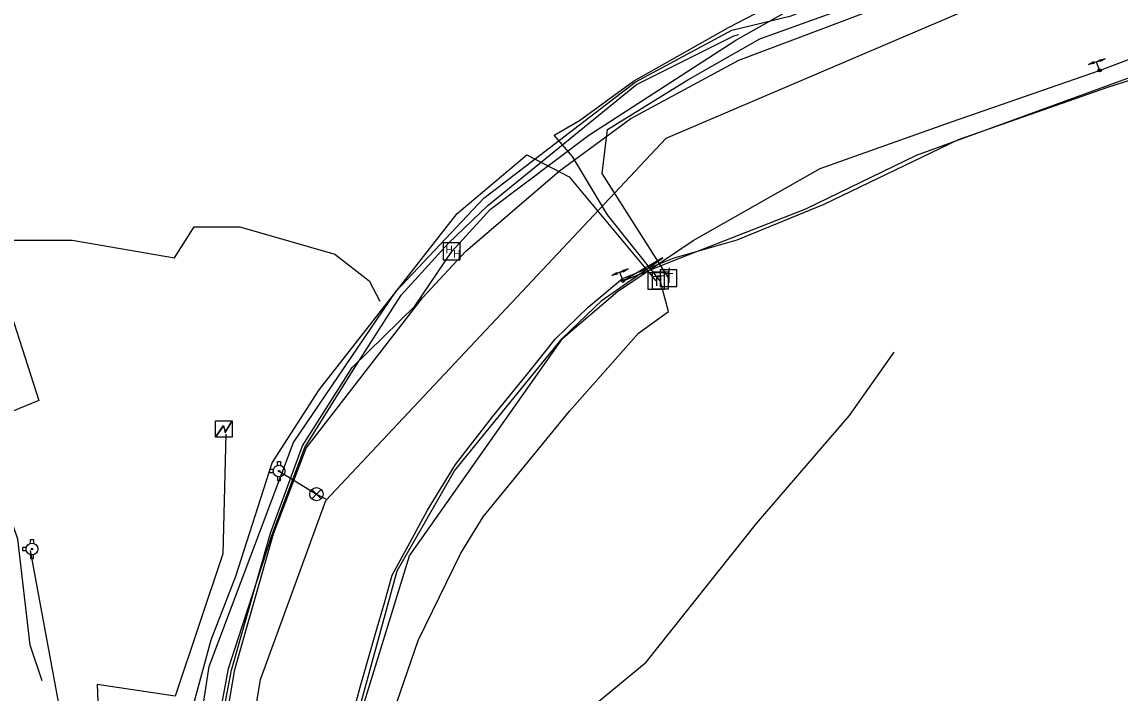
# Model space of a CAD drawing. Extents: x 2070721 to 2083039, y 729290 to 737883.
# Drawn here: x 2080173.8 to 2080544.7, y 734315.9 to 734542.4 of the extents above; entities that cross this region are included whole.
import ezdxf

# ---------------------------------------------------------------- set-up
doc = ezdxf.new("R2010")
doc.units = 0
for name, color, linetype in [('COGO Default Point Elevation', 7, 'Continuous'), ('COGO Default Point Number', 7, 'Continuous'), ('Exist Utilities Power Pole CELL', 7, 'Continuous'), ('Exist Utilities Power Pole Cogo Elevation', 7, 'Continuous'), ('Exist Utilities Power UG Cable Cogo Point CELL', 7, 'Continuous'), ('Exist Utilities Telephone UG Cable SUE LOS C Cogo Comment', 7, 'Continuous'), ('Exist Utilities Telephone UG Cable SUE LOS C Cogo Number', 7, 'Continuous'), ('Exist Utilities Telephone UG FO SUE LOS B Cogo Comment', 7, 'Continuous'), ('Exist Utilities Telephone UG FO SUE LOS B Cogo Number', 7, 'Continuous'), ('Exist Utilities TV Pedestal CELL', 7, 'Continuous'), ('Exist Utilities TV Pedestal Cogo Elevation', 7, 'Continuous'), ('Exist Utilities TV UG Cable Cogo Point CELL', 7, 'Continuous'), ('Exist Utilities TV UG Cable SUE LOS C Cogo Comment', 7, 'Continuous'), ('Exist Utilities TV UG Cable SUE LOS C Cogo Number', 7, 'Continuous'), ('Exist Utilities TV UG Cable SUE LOS C Cogo Point CELL', 7, 'Continuous'), ('Exist Utilities Water UG Line SUE LOS B Cogo Elevation', 7, 'Continuous'), ('Exist Utilities Water Valve CELL', 7, 'Continuous')]:
    doc.layers.add(name, color=color, linetype=linetype)

msp = doc.modelspace()

# ---------------------------------------------------------------- linework, layer by layer
at = {"layer": 'COGO Default Point Elevation'}
msp.add_lwpolyline([(2080274.88, 734384.58), (2080271.73, 734381.43), (2080273.3, 734383), (2080274.88, 734381.43), (2080271.73, 734384.58)], dxfattribs=at)
msp.add_circle((2080273.3, 734383), 2.23, dxfattribs=at)
at = {"layer": 'COGO Default Point Number'}
for p, q in [((2080260.69, 734390.79), (2080260.69, 734390.79)), ((2080177.24, 734364.47), (2080177.24, 734364.47))]:
    msp.add_line(p, q, dxfattribs=at)
for points in [[(2080260.18, 734392.7), (2080260.18, 734393.99), (2080261.2, 734393.99), (2080261.2, 734392.68)], [(2080258.78, 734391.3), (2080257.49, 734391.3), (2080257.49, 734390.28), (2080258.78, 734390.28)], [(2080260.18, 734388.88), (2080260.18, 734387.59), (2080261.2, 734387.59), (2080261.2, 734388.9)], [(2080176.73, 734366.38), (2080176.73, 734367.67), (2080177.75, 734367.67), (2080177.75, 734366.36)], [(2080175.33, 734364.98), (2080174.04, 734364.98), (2080174.04, 734363.96), (2080175.33, 734363.96)], [(2080176.73, 734362.56), (2080176.73, 734361.27), (2080177.75, 734361.27), (2080177.75, 734362.58)]]:
    msp.add_lwpolyline(points, dxfattribs=at)
for centre, radius in [((2080260.69, 734390.79), 1.98), ((2080260.69, 734390.79), 0.243), ((2080177.24, 734364.47), 1.98), ((2080177.24, 734364.47), 0.243)]:
    msp.add_circle(centre, radius, dxfattribs=at)
at = {"layer": 'Exist Utilities Power Pole CELL'}
msp.add_lwpolyline([(2080232.24, 734245.67), (2080237.5, 734254.36), (2080238.66, 734282.35), (2080245.75, 734323.83), (2080258.86, 734369.55), (2080269.86, 734398.57), (2080309.08, 734449.32), (2080323.63, 734464.88), (2080355.41, 734492.16), (2080379.52, 734509.8), (2080416.03, 734529.49), (2080502.71, 734562.3), (2080573.96, 734587.12), (2080616.57, 734603.22), (2080677.16, 734624.99), (2080749, 734651.22), (2080815.57, 734674.3), (2080861.11, 734690.56), (2080923.26, 734714.15), (2080934.26, 734720.97)], dxfattribs=at)
at = {"layer": 'Exist Utilities Power Pole Cogo Elevation'}
msp.add_lwpolyline([(2080537.8, 734526.08), (2080558.84, 734534.05), (2080639.7, 734564.08), (2080660.56, 734567.92), (2080667.78, 734563.47)], dxfattribs=at)
at = {"layer": 'Exist Utilities Power UG Cable Cogo Point CELL'}
for p, q in [((2080539.74, 734530.03), (2080534.11, 734528.06)), ((2080536.78, 734529), (2080539.74, 734530.03)), ((2080537.8, 734526.08), (2080536.78, 734529)), ((2080537.8, 734526.08), (2080537.8, 734526.08))]:
    msp.add_line(p, q, dxfattribs=at)
for points in [[(2080539.74, 734530.03), (2080537.99, 734529.06), (2080538.28, 734529.52), (2080537.82, 734529.68)], [(2080534.11, 734528.06), (2080535.86, 734529.04), (2080535.58, 734528.58), (2080536.04, 734528.41)]]:
    msp.add_lwpolyline(points, close=True, dxfattribs=at)
msp.add_circle((2080537.8, 734526.08), 0.517, dxfattribs=at)
at = {"layer": 'Exist Utilities Telephone UG Cable SUE LOS C Cogo Comment'}
msp.add_lwpolyline([(2080237.92, 734293.08), (2080243.61, 734324.09), (2080258.34, 734369.36), (2080269.39, 734398.77), (2080286.02, 734425.45), (2080301.91, 734450.14), (2080317.89, 734467.75), (2080331.23, 734480.5), (2080381.43, 734521.31), (2080414.27, 734537.75), (2080416.02, 734538.24)], dxfattribs=at)
at = {"layer": 'Exist Utilities Telephone UG Cable SUE LOS C Cogo Number'}
msp.add_line((2080242.08, 734405.14), (2080242.08, 734405.14), dxfattribs=at)
msp.add_lwpolyline([(2080239.24, 734407.75), (2080244.79, 734407.75), (2080244.79, 734402.2), (2080239.24, 734402.2)], close=True, dxfattribs=at)
for points in [[(2080239.24, 734402.2), (2080241.88, 734406.14), (2080242.51, 734403.93), (2080244.79, 734407.75)], [(2080239.31, 734402.2), (2080241.88, 734405.93), (2080242.47, 734403.75), (2080244.79, 734407.6)]]:
    msp.add_lwpolyline(points, dxfattribs=at)
at = {"layer": 'Exist Utilities Telephone UG FO SUE LOS B Cogo Comment'}
for p, q in [((2080392.18, 734455.98), (2080392.18, 734455.98)), ((2080387.98, 734454.99), (2080387.98, 734454.99)), ((2080389.38, 734455.18), (2080389.38, 734455.18))]:
    msp.add_line(p, q, dxfattribs=at)
for points in [[(2080385.26, 734452.16), (2080390.85, 734452.16), (2080390.85, 734457.76), (2080385.26, 734457.76), (2080385.26, 734452.16)], [(2080386.66, 734452.35), (2080392.25, 734452.35), (2080392.25, 734457.95), (2080386.66, 734457.95), (2080386.66, 734452.35)], [(2080389.46, 734453.15), (2080395.05, 734453.15), (2080395.05, 734458.75), (2080389.46, 734458.75), (2080389.46, 734453.15)]]:
    msp.add_lwpolyline(points, dxfattribs=at)
at = {"layer": 'Exist Utilities Telephone UG FO SUE LOS B Cogo Number'}
for p, q in [((2080316.13, 734467.81), (2080316.13, 734462.09)), ((2080321.85, 734467.81), (2080316.13, 734467.81)), ((2080321.85, 734462.09), (2080321.85, 734467.81)), ((2080318.99, 734464.95), (2080318.99, 734464.95)), ((2080316.13, 734462.09), (2080321.85, 734462.09))]:
    msp.add_line(p, q, dxfattribs=at)
at = {"layer": 'Exist Utilities TV Pedestal CELL'}
msp.add_lwpolyline([(2080232.67, 734236.44), (2080273.72, 734233.3), (2080278.08, 734231.48), (2080279.38, 734279.77), (2080300.6, 734357.07), (2080319.92, 734390.91), (2080356.3, 734435.5), (2080369.79, 734448.44), (2080390.27, 734462.8), (2080376.9, 734455.01)], dxfattribs=at)
at = {"layer": 'Exist Utilities TV Pedestal Cogo Elevation'}
for points in [[(2080357.06, 734003.27), (2080353.32, 734006.79), (2080296.63, 734072.2), (2080261.95, 734141.13), (2080251.22, 734185.42), (2080250, 734189.2), (2080244.12, 734248.6), (2080244.13, 734251.5), (2080244.63, 734259.68), (2080245.13, 734264.1), (2080254.44, 734320.44), (2080276.53, 734380.91), (2080391.41, 734503.18), (2080497.9, 734548.7), (2080500.72, 734549.83), (2080585.45, 734578.7), (2080702.53, 734619.89), (2080710.17, 734622.62), (2080743.51, 734634.52), (2080754.26, 734638.28), (2080902.52, 734692.58), (2081024.44, 734735.33)], [(2080260.7, 734390.8), (2080273.35, 734383.02), (2080276.49, 734381.45)], [(2080176.61, 734363.96), (2080186.04, 734312.89), (2080188.09, 734301.77)]]:
    msp.add_lwpolyline(points, dxfattribs=at)
at = {"layer": 'Exist Utilities TV UG Cable Cogo Point CELL'}
for points in [[(2080392.43, 734459.45), (2080392.18, 734455.98), (2080369.79, 734491.21), (2080371.64, 734506.16), (2080398.8, 734522.93), (2080423.1, 734536.76), (2080488.87, 734560.43), (2080551.19, 734581.93), (2080605.97, 734600.8), (2080683.17, 734629.37), (2080713.38, 734633.09), (2080745.42, 734609.78), (2080760.77, 734576.63), (2080781.91, 734561.06), (2080789.84, 734547.84), (2080795.45, 734523.96), (2080798.47, 734502.81), (2080795.45, 734476.11), (2080787.39, 734456.13)], [(2080389.44, 734455.05), (2080371.58, 734477.3), (2080359.8, 734497.02), (2080353.64, 734504.17), (2080362.14, 734509.13), (2080380.41, 734522.38), (2080412.54, 734540.56), (2080431.18, 734550.33), (2080456.15, 734565.37), (2080500.74, 734587.65), (2080527.18, 734594.58)], [(2080179.48, 734239.75), (2080182.79, 734239.75), (2080204.44, 734237.74), (2080223.27, 734244.14), (2080227.06, 734249.97), (2080225.75, 734270.22), (2080228.23, 734298.53), (2080237.75, 734333.83), (2080246.14, 734355.32), (2080258.39, 734393.6), (2080274.22, 734418.19), (2080320.87, 734477.75), (2080344.36, 734497.56), (2080358.62, 734490.18), (2080387.98, 734454.99)], [(2080294.22, 734238.68), (2080294.22, 734255.9), (2080294.22, 734291.26), (2080298.27, 734306.08), (2080307.66, 734333.57), (2080322.1, 734363.11), (2080329.68, 734375.34), (2080358.78, 734411), (2080382.14, 734437.37), (2080392.23, 734444.72), (2080389.38, 734455.18)]]:
    msp.add_lwpolyline(points, dxfattribs=at)
at = {"layer": 'Exist Utilities TV UG Cable SUE LOS C Cogo Comment'}
for points in [[(2080374.96, 734451.44), (2080400.56, 734468.64), (2080443.44, 734492.96), (2080487.87, 734508.65), (2080537.8, 734526.08)], [(2080156.43, 734468.74), (2080190.75, 734468.74), (2080225.32, 734462.79), (2080232.03, 734473.2), (2080247.47, 734473.2), (2080279.52, 734463.97), (2080291.1, 734455.07), (2080294.67, 734448.18)], [(2079930.03, 734379.03), (2079973.5, 734401.57), (2080005.21, 734418.36), (2080027.53, 734423.19), (2080076.32, 734443.97), (2080107.09, 734455.28), (2080156.31, 734468.93), (2080165.35, 734458.46), (2080179.56, 734414.66), (2080139.33, 734398.19), (2080109.12, 734387.94), (2080086.12, 734381.02)], [(2080234.71, 734179.89), (2080280.62, 734187.44), (2080282.92, 734196.34), (2080279.43, 734280.03), (2080304.76, 734362.13), (2080356.55, 734435.67), (2080374.96, 734451.44)], [(2080370.98, 734154.39), (2080361.51, 734212.64), (2080345.43, 734289.41), (2080345.93, 734294.31), (2080384.7, 734326.31), (2080421.96, 734373.11), (2080453.41, 734409.54), (2080468.5, 734430.99)], [(2080242.66, 734403.28), (2080241.67, 734362.84), (2080225.56, 734314.83), (2080199.19, 734318.7), (2080200.86, 734278.87), (2080222.27, 734229.12), (2080235.32, 734178.97)], [(2080180.65, 734319.97), (2080176.58, 734332.03), (2080172.45, 734367.8), (2080164.56, 734390.43)]]:
    msp.add_lwpolyline(points, dxfattribs=at)
at = {"layer": 'Exist Utilities TV UG Cable SUE LOS C Cogo Number'}
msp.add_lwpolyline([(2080278.08, 734231.48), (2080277, 734239.67), (2080277, 734275.25), (2080279.3, 734284.9), (2080288.08, 734317.87), (2080293.24, 734335.92), (2080296.25, 734346.26), (2080298.88, 734355.59), (2080304.96, 734366.83), (2080310.77, 734377.58), (2080320.31, 734392.98), (2080332.74, 734409.06), (2080345.11, 734424.32), (2080353.93, 734435.35), (2080365.15, 734446.1), (2080376.65, 734455.86), (2080394.1, 734462.75), (2080415.44, 734468.86), (2080444.8, 734480.86), (2080490.14, 734502.72), (2080540.63, 734520.42), (2080564.59, 734528.02)], dxfattribs=at)
at = {"layer": 'Exist Utilities TV UG Cable SUE LOS C Cogo Point CELL'}
for points in [[(2080235.11, 734249.36), (2080234.94, 734252.48), (2080236.58, 734281.87), (2080244.62, 734323.58), (2080257.8, 734369.84), (2080268.59, 734399.28), (2080285.42, 734425.78), (2080306.49, 734446.52), (2080318.99, 734464.89), (2080332.07, 734479.26), (2080365.28, 734504.24), (2080415, 734536.31), (2080432.75, 734546.34), (2080471.85, 734557.5), (2080502.31, 734568.65), (2080534.18, 734580.2), (2080570.94, 734591.77), (2080576.66, 734593.81), (2080717.24, 734648.01)], [(2080228.28, 734243.43), (2080230.55, 734282.39), (2080237.1, 734324.84), (2080265.61, 734400.42), (2080300.19, 734451.55), (2080329.83, 734482.91), (2080380.99, 734522.11), (2080413.6, 734539.64), (2080433.63, 734544.47), (2080470.56, 734559.5), (2080533.58, 734581.77), (2080652.68, 734625.4)]]:
    msp.add_lwpolyline(points, dxfattribs=at)
at = {"layer": 'Exist Utilities Water UG Line SUE LOS B Cogo Elevation'}
msp.add_lwpolyline([(2080376.9, 734455.01), (2080393.72, 734461.75), (2080438.63, 734479.28), (2080476.05, 734497.46), (2080571.1, 734532.14), (2080615.4, 734550.71)], dxfattribs=at)
at = {"layer": 'Exist Utilities Water Valve CELL'}
for p, q in [((2080378.66, 734459.04), (2080373.12, 734456.82)), ((2080375.75, 734457.87), (2080378.66, 734459.04)), ((2080376.9, 734455.01), (2080375.75, 734457.87)), ((2080376.9, 734455.01), (2080376.9, 734455.01))]:
    msp.add_line(p, q, dxfattribs=at)
for points in [[(2080373.12, 734456.82), (2080374.83, 734457.87), (2080374.56, 734457.4), (2080375.03, 734457.26)], [(2080378.66, 734459.04), (2080376.96, 734457.99), (2080377.22, 734458.46), (2080376.75, 734458.61)]]:
    msp.add_lwpolyline(points, close=True, dxfattribs=at)
msp.add_circle((2080376.9, 734455.01), 0.517, dxfattribs=at)

# ---------------------------------------------------------------- texts
at = {"layer": 'Exist Utilities Telephone UG FO SUE LOS B Cogo Comment'}
for p in [(2080386.85, 734453.28), (2080388.25, 734453.47), (2080391.05, 734454.27)]:
    msp.add_text('T', height=3.42, dxfattribs=at).set_placement(p)
at = {"layer": 'Exist Utilities Telephone UG FO SUE LOS B Cogo Number'}
for p in [(2080316.91, 734464.36), (2080319.48, 734462.89)]:
    msp.add_text('H', height=2.5, dxfattribs=at).set_placement(p)

doc.saveas('drawing.dxf')
